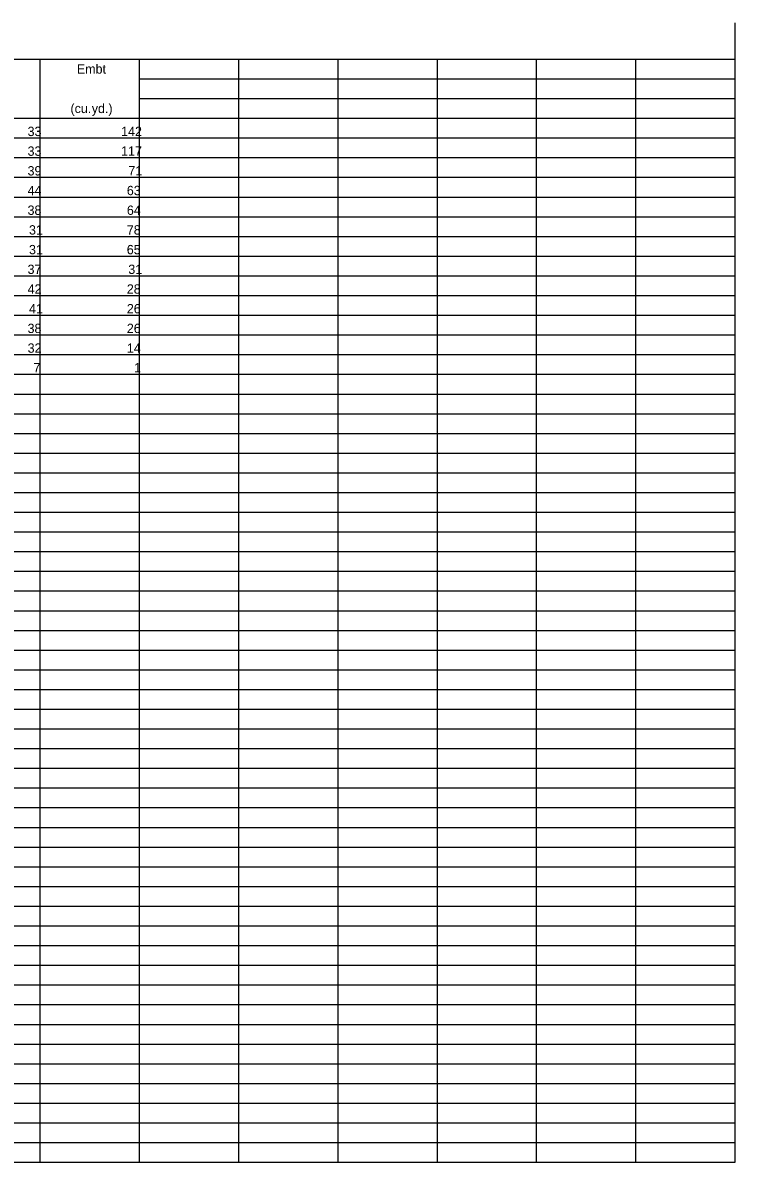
# Model space of a CAD drawing. Extents: x 239 to 408, y 686 to 906.
# Drawn here: x 346.3 to 406.1, y 686 to 781.7 of the extents above; entities that cross this region are included whole.
import ezdxf

# ---------------------------------------------------------------- set-up
doc = ezdxf.new("R2010")
doc.units = 0
doc.layers.add('Default', color=7, linetype='Continuous')

msp = doc.modelspace()

# ---------------------------------------------------------------- linework, layer by layer
at = {"layer": 'Default'}
for p, q in [((406.087, 778.659), (406.087, 781.713)), ((256.088, 778.659), (406.087, 778.659)), ((256.088, 778.659), (406.087, 778.659)), ((347.754, 752.196), (347.754, 778.659)), ((347.754, 773.697), (347.754, 778.659)), ((356.088, 752.196), (356.088, 778.659)), ((356.088, 752.196), (356.088, 778.659)), ((364.421, 686.039), (364.421, 778.659)), ((364.421, 686.039), (364.421, 778.659)), ((372.754, 686.039), (372.754, 778.659)), ((381.087, 686.039), (381.087, 778.659)), ((389.421, 686.039), (389.421, 778.659)), ((397.754, 686.039), (397.754, 778.659)), ((397.754, 686.039), (397.754, 778.659)), ((406.087, 686.039), (406.087, 778.659)), ((356.088, 777.005), (406.087, 777.005)), ((356.088, 775.351), (406.087, 775.351)), ((256.088, 773.697), (356.088, 773.697)), ((356.088, 773.697), (406.087, 773.697)), ((256.088, 772.043), (356.088, 772.043)), ((356.088, 772.043), (406.087, 772.043)), ((256.088, 770.39), (356.088, 770.39)), ((356.088, 770.39), (406.087, 770.39)), ((256.088, 768.736), (356.088, 768.736)), ((306.088, 768.736), (356.088, 768.736)), ((356.088, 768.736), (406.087, 768.736)), ((256.088, 767.082), (356.088, 767.082)), ((356.088, 767.082), (406.087, 767.082)), ((306.088, 765.428), (356.088, 765.428)), ((356.088, 765.428), (406.087, 765.428)), ((322.754, 763.774), (356.088, 763.774)), ((356.088, 763.774), (406.087, 763.774)), ((256.088, 762.12), (356.088, 762.12)), ((356.088, 762.12), (406.087, 762.12)), ((331.088, 760.466), (356.088, 760.466)), ((356.088, 760.466), (406.087, 760.466)), ((331.088, 758.812), (356.088, 758.812)), ((356.088, 758.812), (406.087, 758.812)), ((256.088, 757.158), (356.088, 757.158)), ((356.088, 757.158), (406.087, 757.158)), ((256.088, 755.504), (356.088, 755.504)), ((356.088, 755.504), (406.087, 755.504)), ((256.088, 753.85), (356.088, 753.85)), ((356.088, 753.85), (406.087, 753.85)), ((256.088, 752.196), (356.088, 752.196)), ((331.088, 752.196), (356.088, 752.196)), ((347.754, 686.039), (347.754, 752.196)), ((356.088, 752.196), (406.087, 752.196)), ((356.088, 686.039), (356.088, 752.196)), ((331.088, 750.542), (406.087, 750.542)), ((331.088, 748.888), (406.087, 748.888)), ((331.088, 747.234), (406.087, 747.234)), ((331.088, 745.581), (406.087, 745.581)), ((331.088, 743.927), (406.087, 743.927)), ((331.088, 742.273), (406.087, 742.273)), ((331.088, 740.619), (406.087, 740.619)), ((331.088, 738.965), (406.087, 738.965)), ((331.088, 737.311), (406.087, 737.311)), ((331.088, 735.657), (406.087, 735.657)), ((331.088, 734.003), (406.087, 734.003)), ((331.088, 732.349), (406.087, 732.349)), ((331.088, 730.695), (406.087, 730.695)), ((331.088, 729.041), (406.087, 729.041)), ((331.088, 727.387), (406.087, 727.387)), ((331.088, 725.733), (406.087, 725.733)), ((331.088, 724.079), (406.087, 724.079)), ((331.088, 722.425), (406.087, 722.425)), ((331.088, 720.771), (406.087, 720.771)), ((331.088, 719.118), (406.087, 719.118)), ((331.088, 717.464), (406.087, 717.464)), ((331.088, 715.81), (406.087, 715.81)), ((331.088, 714.156), (406.087, 714.156)), ((331.088, 712.502), (406.087, 712.502)), ((331.088, 710.848), (406.087, 710.848)), ((331.088, 709.194), (406.087, 709.194)), ((331.088, 707.54), (406.087, 707.54)), ((331.088, 705.886), (406.087, 705.886)), ((331.088, 704.232), (406.087, 704.232)), ((331.088, 702.578), (406.087, 702.578)), ((331.088, 700.924), (406.087, 700.924)), ((331.088, 699.27), (406.087, 699.27)), ((331.088, 697.616), (406.087, 697.616)), ((331.088, 695.962), (406.087, 695.962)), ((331.088, 694.309), (406.087, 694.309)), ((331.088, 692.655), (406.087, 692.655)), ((331.088, 691.001), (406.087, 691.001)), ((331.088, 689.347), (406.087, 689.347)), ((331.088, 687.693), (406.087, 687.693)), ((256.088, 686.039), (406.087, 686.039))]:
    msp.add_line(p, q, dxfattribs=at)

# ---------------------------------------------------------------- texts
for s, height, p in [('Embt', 0.7829, (350.832, 777.441)), ('(cu.', 0.7829, (350.297, 774.133)), (' yd.)', 0.7829, (351.792, 774.133)), ('33', 0.7829, (346.694, 772.2)), ('142', 0.7829, (354.547, 772.2)), ('33', 0.7829, (346.694, 770.546)), ('117', 0.7829, (354.541, 770.546)), ('39', 0.7829, (346.693, 768.892)), ('71', 0.7829, (355.148, 768.892)), ('44', 0.7829, (346.697, 767.238)), ('63', 0.7829, (355.027, 767.238)), ('38', 0.7829, (346.693, 765.584)), ('64', 0.7829, (355.03, 765.584)), ('31', 0.7829, (346.815, 763.93)), ('78', 0.7829, (355.026, 763.93)), ('31', 0.7829, (346.815, 762.276)), ('65', 0.7829, (355.022, 762.276)), ('37', 0.7829, (346.694, 760.623)), ('31', 0.7829, (355.148, 760.623)), ('42', 0.7829, (346.7, 758.969)), ('28', 0.7829, (355.026, 758.969)), ('41', 0.7829, (346.815, 757.315)), ('26', 0.7829, (355.027, 757.315)), ('38', 0.7829, (346.693, 755.661)), ('26', 0.7829, (355.027, 755.661)), ('32', 0.7829, (346.7, 754.007)), ('14', 0.7829, (355.03, 754.007)), ('7', 0.783, (347.18, 752.353)), ('1', 0.783, (355.635, 752.353))]:
    msp.add_text(s, height=height, dxfattribs=at).set_placement(p)

doc.saveas('drawing.dxf')
